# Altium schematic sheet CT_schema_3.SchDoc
size 410 x 311 mm
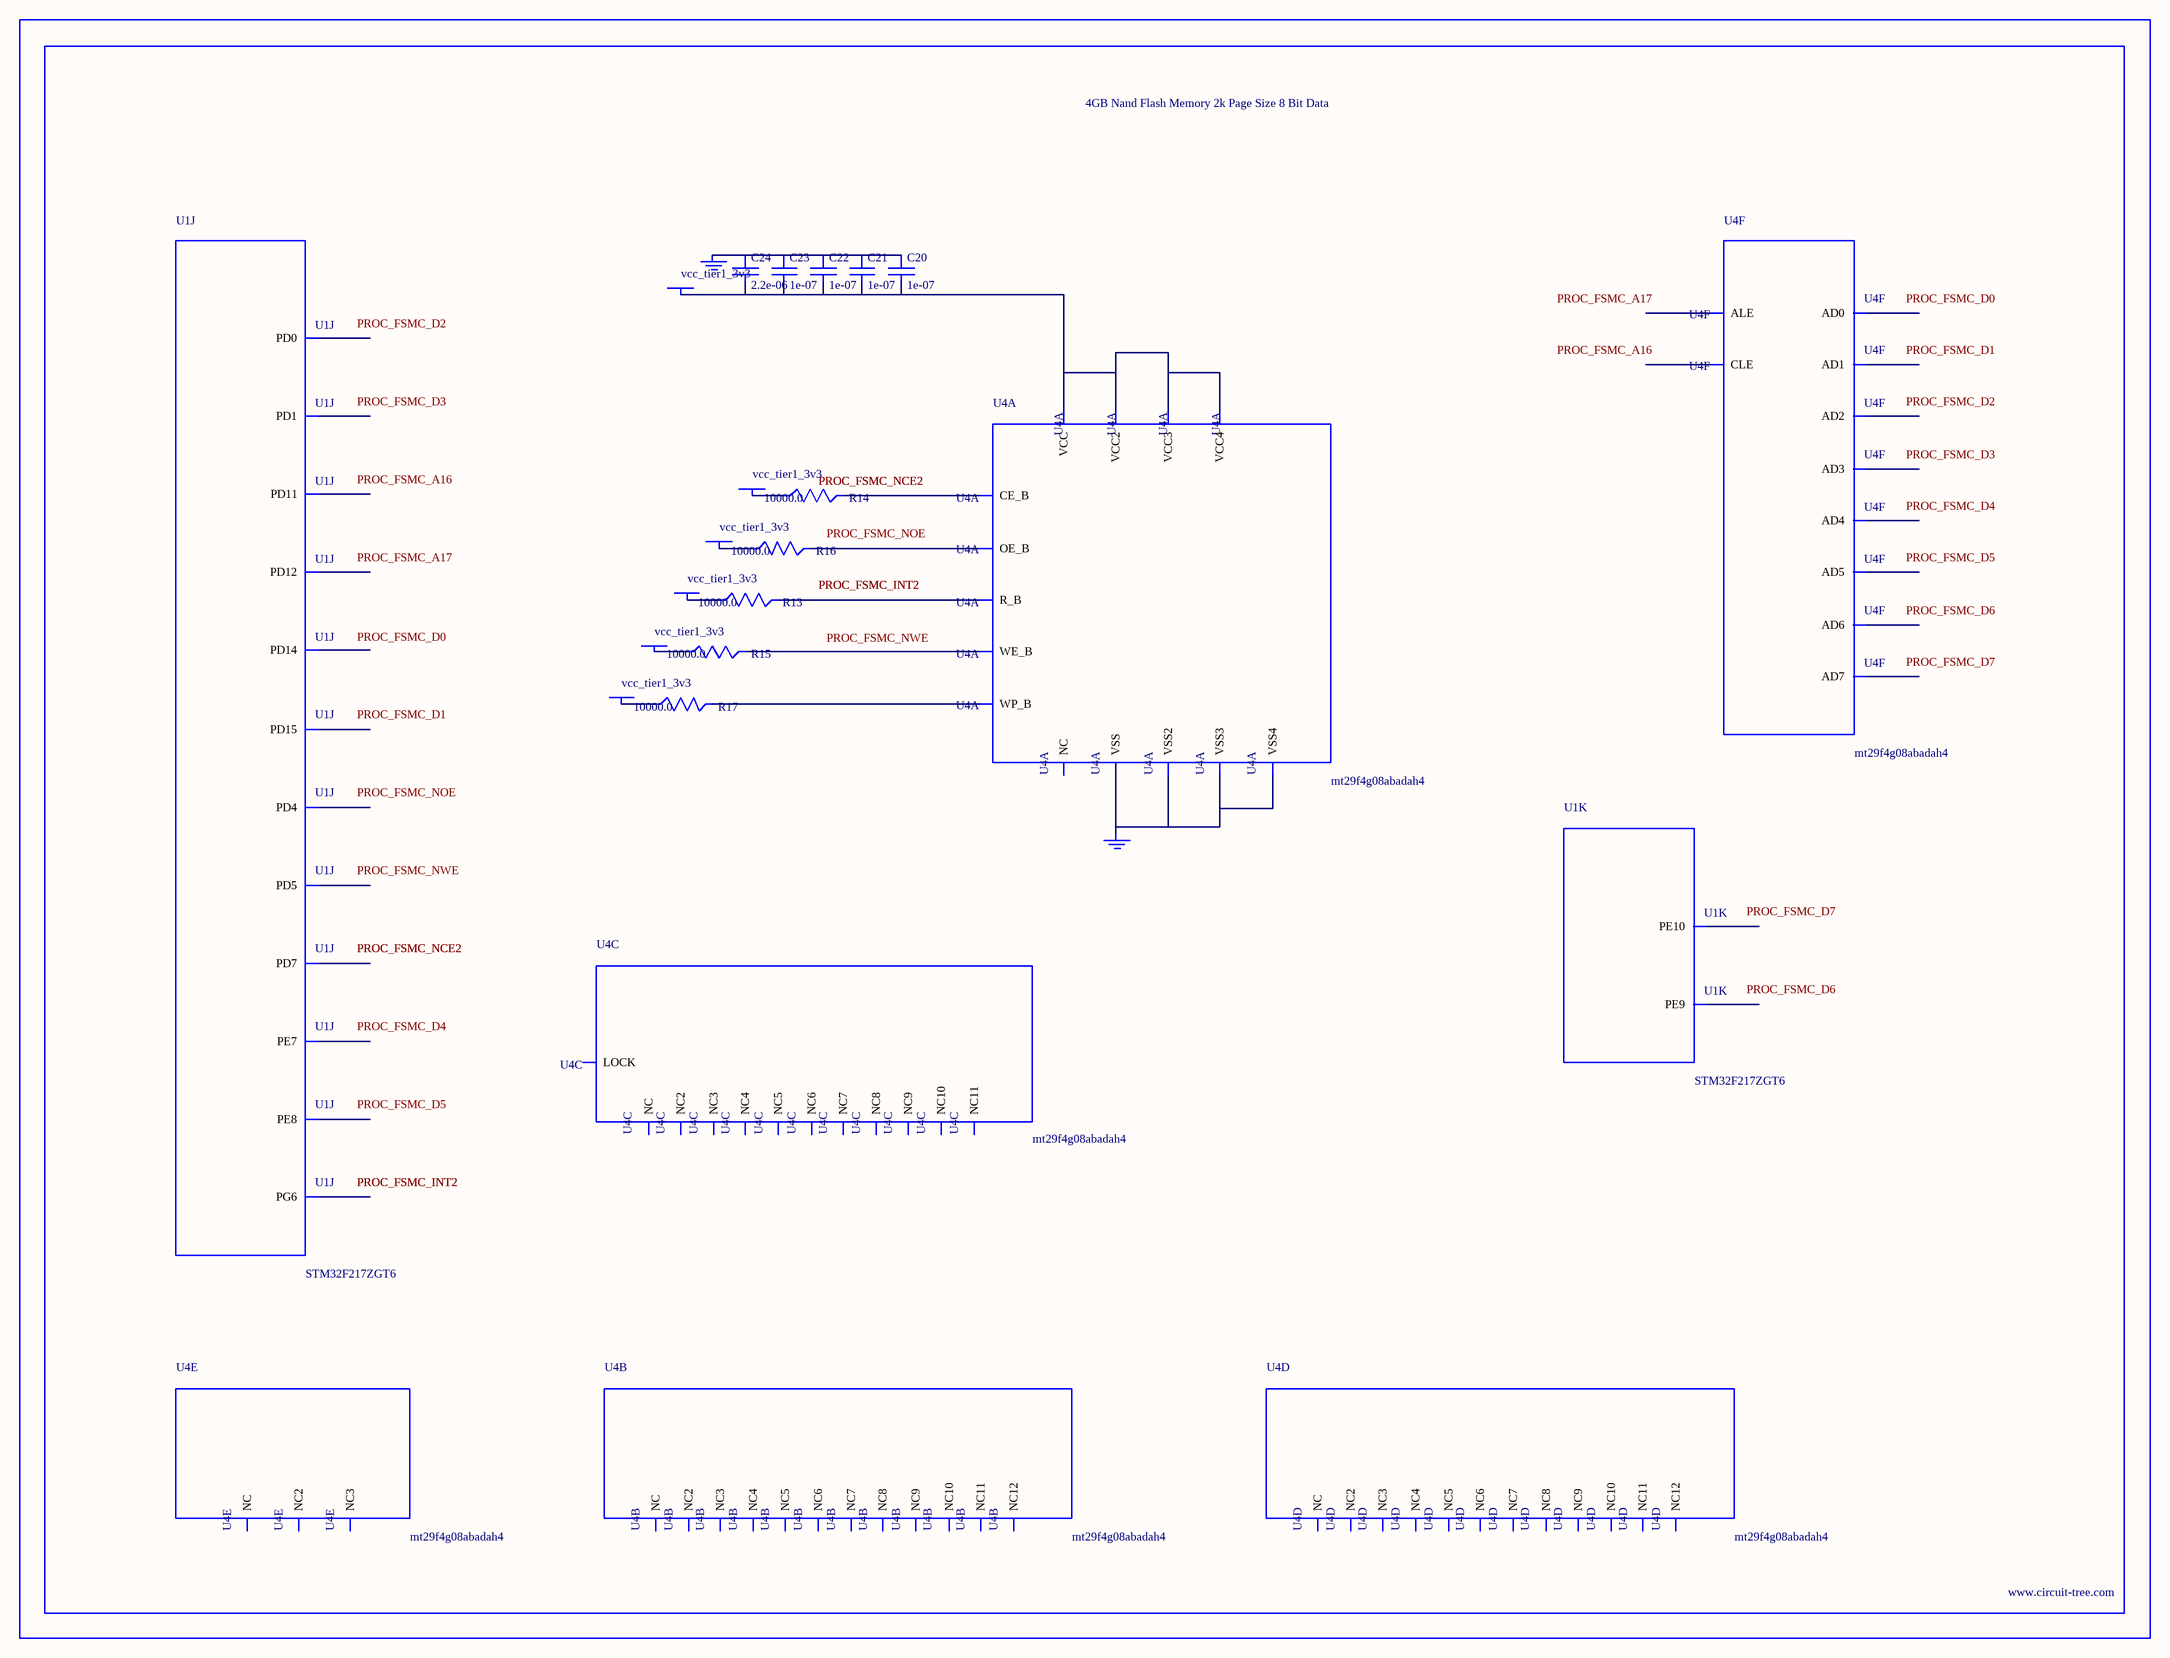
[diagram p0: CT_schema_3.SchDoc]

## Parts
BORDER2  (no value)
C20  1e-07  [C0402]
C21  1e-07  [C0402]
C22  1e-07  [C0402]
C23  1e-07  [C0402]
C24  2.2e-06  [C0603]
GND_INSTANCE_2_0  (no value)
GND_INSTANCE_2_1  (no value)
POWER_INSTANCE_2_0  vcc_tier1_3v3
POWER_INSTANCE_2_1  vcc_tier1_3v3
POWER_INSTANCE_2_2  vcc_tier1_3v3
POWER_INSTANCE_2_3  vcc_tier1_3v3
POWER_INSTANCE_2_4  vcc_tier1_3v3
POWER_INSTANCE_2_5  vcc_tier1_3v3
R13  10000.0  [R0603]
R14  10000.0  [R0603]
R15  10000.0  [R0603]
R16  10000.0  [R0603]
R17  10000.0  [R0603]
U1  STM32F217ZGT6  [LQFP144]  (parts J,K of 13)
U4  mt29f4g08abadah4  [VFBGA-63]  (parts A,B,C,D,E,F of 6)

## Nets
NetC20_1: C20.1 C21.1 C22.1 C23.1 C24.1 GND_INSTANCE_2_0.0(GND)
NetC20_2: C20.2 C21.2 C22.2 C23.2 C24.2 POWER_INSTANCE_2_0.0(PWR) U4.D3(VCC) U4.G4(VCC2) U4.H8(VCC3) U4.J6(VCC4)
NetGND_INSTANCE_2_1_0: GND_INSTANCE_2_1.0(GND) U4.C5(VSS) U4.F7(VSS2) U4.K3(VSS3) U4.K8(VSS4)
NetPOWER_INSTANCE_2_1_0: POWER_INSTANCE_2_1.0(PWR) R13.1
NetPOWER_INSTANCE_2_2_0: POWER_INSTANCE_2_2.0(PWR) R14.1
NetPOWER_INSTANCE_2_3_0: POWER_INSTANCE_2_3.0(PWR) R15.1
NetPOWER_INSTANCE_2_4_0: POWER_INSTANCE_2_4.0(PWR) R16.1
NetPOWER_INSTANCE_2_5_0: POWER_INSTANCE_2_5.0(PWR) R17.1
NetR13_2: R13.2 U4.C8(R_B)
NetR14_2: R14.2 U4.C6(CE_B)
NetR15_2: R15.2 U4.C7(WE_B)
NetR16_2: R16.2 U4.D4(OE_B)
NetR17_2: R17.2 U4.C3(WP_B)

Not connected (* = marked no-connect by the designer): U1 58(PE7) 59(PE8) 60(PE9) 63(PE10) 80(PD11) 81(PD12) 85(PD14) 86(PD15) 91(PG6) 114(PD0) 115(PD1) 118(PD4) 119(PD5) 123(PD7); U4 A1(NC) A2(NC3) A9(NC4) A10(NC2) B1(NC5) B9(NC7) B10(NC6) C4(ALE) D5(CLE) D6(NC8) D7(NC9) D8(NC10) E3(NC11) E4(NC12) E5(NC) E6(NC2) E7(NC3) E8(NC4) F3(NC5) F4(NC6) F5(NC7) F6(NC8) F8(NC9) G3(NC) G5(LOCK) G6(NC10) G7(NC11) G8(NC) H3(NC2) H4(AD0) H5(NC3) H6(NC4) H7(NC5) J3(NC6) J4(AD1) J5(NC7) J7(AD5) J8(AD7) K4(AD2) K5(AD3) K6(AD4) K7(AD6) L1(NC8) L2(NC10) L9(NC11) L10(NC9) M1(NC12) M2(NC2) M9(NC3) M10(NC)

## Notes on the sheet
- Labels drawn without touching a wire or pin: PROC_FSMC_A16, PROC_FSMC_A17, PROC_FSMC_D0, PROC_FSMC_D1, PROC_FSMC_D2, PROC_FSMC_D3, PROC_FSMC_D4, PROC_FSMC_D5, PROC_FSMC_D6, PROC_FSMC_D7, PROC_FSMC_NOE, PROC_FSMC_NWE

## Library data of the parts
BORDER2 = BORDER_PAGE2
C20-C23 = C0402C104K3RACTU
C24 = C0603C225K8RACTU
GND_INSTANCE_2_0 GND_INSTANCE_2_1 = GND
POWER_INSTANCE_2_0-POWER_INSTANCE_2_5 = PWR
R13-R17 = RC0603JR-0710KL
